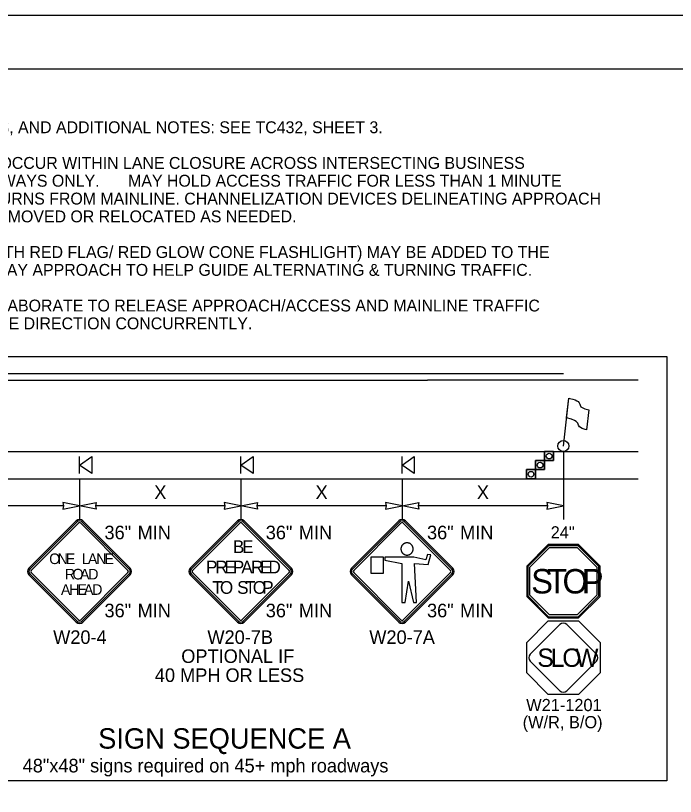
# Model space of a CAD drawing. Extents: x 99999.1 to 100095.7, y 99995 to 100010.7.
# Drawn here: x 100061.313 to 100065.2, y 100006.089 to 100010.687 of the extents above; entities that cross this region are included whole.
import ezdxf

# ---------------------------------------------------------------- set-up
doc = ezdxf.new("R2010")
doc.units = 0
for name, color, linetype in [('RD_ED_ShoulderPavedEdge', 7, 'Continuous'), ('RD_MK_LineDblYellowCenter', 7, 'Continuous'), ('RD_MK_LineEdgeWhite', 7, 'Continuous'), ('RD_MK_LineNoPass', 7, 'Continuous'), ('RD_MK_LineSkipCenter', 7, 'Continuous'), ('SH_DE_DetailHeading2Text', 7, 'Continuous'), ('SH_GI_GeneralNotesBodyText', 7, 'Continuous'), ('SH_GI_PlotLimits', 7, 'Continuous'), ('SH_GI_SheetBorder', 7, 'Continuous'), ('TR_SN_ConstructionSigns', 7, 'Continuous'), ('TR_WZ_FlaggingStation', 7, 'Continuous'), ('TR_WZ_PortableSignMountBlk-Org', 7, 'Continuous'), ('TR_WZ_TrafficCone', 7, 'Continuous'), ('TR_WZ_WorkZoneDetails', 7, 'Continuous'), ('TR_WZ_WorkZoneTextCurrent', 7, 'Continuous')]:
    doc.layers.add(name, color=color, linetype=linetype)

msp = doc.modelspace()

# ---------------------------------------------------------------- linework, layer by layer
at = {"layer": 'RD_ED_ShoulderPavedEdge'}
msp.add_line((100060.3, 100007.9602), (100064.9804, 100007.9602), dxfattribs=at)
at = {"layer": 'RD_MK_LineDblYellowCenter'}
for p, q in [((100060.3, 100008.5802), (100063.7402, 100008.5802)), ((100060.3, 100008.5402), (100063.7402, 100008.5402))]:
    msp.add_line(p, q, dxfattribs=at)
at = {"layer": 'RD_MK_LineEdgeWhite'}
msp.add_line((100060.3, 100008.1202), (100064.9804, 100008.1202), dxfattribs=at)
at = {"layer": 'RD_MK_LineNoPass'}
msp.add_line((100063.7402, 100008.5802), (100064.5402, 100008.5802), dxfattribs=at)
at = {"layer": 'RD_MK_LineSkipCenter'}
msp.add_lwpolyline([(100064.9804, 100008.5402), (100063.7402, 100008.5402)], dxfattribs=at)
at = {"layer": 'SH_GI_PlotLimits'}
msp.add_lwpolyline([(100059.0625, 99999.6875), (100076.0625, 99999.6875), (100076.0625, 100010.6875), (100059.0625, 100010.6875)], close=True, dxfattribs=at)
at = {"layer": 'SH_GI_SheetBorder'}
msp.add_line((100060, 100010.375), (100075.75, 100010.375), dxfattribs=at)
at = {"layer": 'TR_SN_ConstructionSigns'}
for p, q in [((100061.6703, 100007.712), (100061.3919, 100007.4336)), ((100061.6758, 100007.7065), (100061.3974, 100007.428)), ((100061.4051, 100007.4203), (100061.6835, 100007.6987)), ((100061.6968, 100007.6987), (100061.9752, 100007.4203)), ((100061.9829, 100007.428), (100061.7045, 100007.7065)), ((100061.9885, 100007.4336), (100061.71, 100007.712)), ((100062.6203, 100007.712), (100062.3419, 100007.4336)), ((100062.6258, 100007.7065), (100062.3474, 100007.428)), ((100062.3551, 100007.4203), (100062.6335, 100007.6987)), ((100062.6468, 100007.6987), (100062.9252, 100007.4203)), ((100062.9329, 100007.428), (100062.6545, 100007.7065)), ((100062.9385, 100007.4336), (100062.66, 100007.712)), ((100063.5703, 100007.712), (100063.2919, 100007.4336)), ((100063.5758, 100007.7065), (100063.2974, 100007.428)), ((100063.3051, 100007.4203), (100063.5835, 100007.6987)), ((100063.5968, 100007.6987), (100063.8752, 100007.4203)), ((100063.8829, 100007.428), (100063.6045, 100007.7065)), ((100063.8885, 100007.4336), (100063.61, 100007.712)), ((100063.6071, 100007.5803), (100063.6053, 100007.5796)), ((100063.6089, 100007.5809), (100063.6071, 100007.5803)), ((100063.6108, 100007.5814), (100063.6089, 100007.5809)), ((100063.6127, 100007.5818), (100063.6108, 100007.5814)), ((100063.6146, 100007.5821), (100063.6127, 100007.5818)), ((100063.6164, 100007.5823), (100063.6146, 100007.5821)), ((100063.6184, 100007.5824), (100063.6164, 100007.5823)), ((100063.6203, 100007.5824), (100063.6184, 100007.5824)), ((100063.6222, 100007.5823), (100063.6203, 100007.5824)), ((100063.6241, 100007.5821), (100063.6222, 100007.5823)), ((100063.626, 100007.5818), (100063.6241, 100007.5821)), ((100063.6279, 100007.5814), (100063.626, 100007.5818)), ((100063.6297, 100007.5809), (100063.6279, 100007.5814)), ((100063.6316, 100007.5803), (100063.6297, 100007.5809)), ((100063.6333, 100007.5796), (100063.6316, 100007.5803)), ((100063.5835, 100007.5502), (100063.5833, 100007.5483)), ((100063.5833, 100007.5483), (100063.5833, 100007.5464)), ((100063.5833, 100007.5464), (100063.5833, 100007.5445)), ((100063.5833, 100007.5445), (100063.5835, 100007.5426)), ((100063.5838, 100007.5522), (100063.5835, 100007.5502)), ((100063.5835, 100007.5426), (100063.5838, 100007.5407)), ((100063.5842, 100007.554), (100063.5838, 100007.5522)), ((100063.5838, 100007.5407), (100063.5842, 100007.5388)), ((100063.5846, 100007.5559), (100063.5842, 100007.554)), ((100063.5842, 100007.5388), (100063.5846, 100007.5369)), ((100063.5852, 100007.5577), (100063.5846, 100007.5559)), ((100063.5846, 100007.5369), (100063.5852, 100007.5351)), ((100063.5858, 100007.5595), (100063.5852, 100007.5577)), ((100063.5852, 100007.5351), (100063.5858, 100007.5333)), ((100063.5865, 100007.5613), (100063.5858, 100007.5595)), ((100063.5873, 100007.563), (100063.5865, 100007.5613)), ((100063.5883, 100007.5647), (100063.5873, 100007.563)), ((100063.5894, 100007.5664), (100063.5883, 100007.5647)), ((100063.5904, 100007.5679), (100063.5894, 100007.5664)), ((100063.5916, 100007.5694), (100063.5904, 100007.5679)), ((100063.5929, 100007.5709), (100063.5916, 100007.5694)), ((100063.5942, 100007.5722), (100063.5929, 100007.5709)), ((100063.5956, 100007.5735), (100063.5942, 100007.5722)), ((100063.5971, 100007.5747), (100063.5956, 100007.5735)), ((100063.5986, 100007.5759), (100063.5971, 100007.5747)), ((100063.6002, 100007.5769), (100063.5986, 100007.5759)), ((100063.6019, 100007.5779), (100063.6002, 100007.5769)), ((100063.6036, 100007.5788), (100063.6019, 100007.5779)), ((100063.6053, 100007.5796), (100063.6036, 100007.5788)), ((100063.6351, 100007.5788), (100063.6333, 100007.5796)), ((100063.6368, 100007.5779), (100063.6351, 100007.5788)), ((100063.6385, 100007.5769), (100063.6368, 100007.5779)), ((100063.64, 100007.5759), (100063.6385, 100007.5769)), ((100063.6416, 100007.5747), (100063.64, 100007.5759)), ((100063.643, 100007.5735), (100063.6416, 100007.5747)), ((100063.6445, 100007.5722), (100063.643, 100007.5735)), ((100063.6458, 100007.5709), (100063.6445, 100007.5722)), ((100063.647, 100007.5694), (100063.6458, 100007.5709)), ((100063.6482, 100007.5679), (100063.647, 100007.5694)), ((100063.6494, 100007.5664), (100063.6482, 100007.5679)), ((100063.6504, 100007.5647), (100063.6494, 100007.5664)), ((100063.6513, 100007.563), (100063.6504, 100007.5647)), ((100063.6521, 100007.5613), (100063.6513, 100007.563)), ((100063.6529, 100007.5595), (100063.6521, 100007.5613)), ((100063.6535, 100007.5577), (100063.6529, 100007.5595)), ((100063.6529, 100007.5333), (100063.6535, 100007.5351)), ((100063.6541, 100007.5559), (100063.6535, 100007.5577)), ((100063.6535, 100007.5351), (100063.6541, 100007.5369)), ((100063.6545, 100007.554), (100063.6541, 100007.5559)), ((100063.6541, 100007.5369), (100063.6545, 100007.5388)), ((100063.6549, 100007.5522), (100063.6545, 100007.554)), ((100063.6545, 100007.5388), (100063.6549, 100007.5407)), ((100063.6552, 100007.5502), (100063.6549, 100007.5522)), ((100063.6549, 100007.5407), (100063.6552, 100007.5426)), ((100063.6553, 100007.5483), (100063.6552, 100007.5502)), ((100063.6552, 100007.5426), (100063.6553, 100007.5445)), ((100063.6554, 100007.5464), (100063.6553, 100007.5483)), ((100063.6553, 100007.5445), (100063.6554, 100007.5464)), ((100064.4506, 100007.5722), (100064.3241, 100007.4457)), ((100064.4534, 100007.5655), (100064.3308, 100007.4429)), ((100064.3421, 100007.4383), (100064.4581, 100007.5542)), ((100064.6295, 100007.5722), (100064.4506, 100007.5722)), ((100064.6267, 100007.5655), (100064.4534, 100007.5655)), ((100064.4581, 100007.5542), (100064.6221, 100007.5542)), ((100064.6221, 100007.5542), (100064.7381, 100007.4383)), ((100064.7493, 100007.4429), (100064.6267, 100007.5655)), ((100064.7561, 100007.4457), (100064.6295, 100007.5722)), ((100063.4059, 100007.4991), (100063.4059, 100007.4044)), ((100063.4812, 100007.4991), (100063.4059, 100007.4991)), ((100063.4812, 100007.4044), (100063.4812, 100007.4991)), ((100063.6596, 100007.4991), (100063.4882, 100007.4991)), ((100063.4882, 100007.4991), (100063.4882, 100007.481)), ((100063.5858, 100007.5333), (100063.5865, 100007.5315)), ((100063.5865, 100007.5315), (100063.5873, 100007.5298)), ((100063.5873, 100007.5298), (100063.5883, 100007.5281)), ((100063.5883, 100007.5281), (100063.5894, 100007.5265)), ((100063.5894, 100007.5265), (100063.5904, 100007.5249)), ((100063.5904, 100007.5249), (100063.5916, 100007.5234)), ((100063.5916, 100007.5234), (100063.5929, 100007.522)), ((100063.5929, 100007.522), (100063.5942, 100007.5206)), ((100063.5942, 100007.5206), (100063.5956, 100007.5193)), ((100063.5956, 100007.5193), (100063.5971, 100007.5181)), ((100063.5971, 100007.5181), (100063.5986, 100007.5169)), ((100063.5986, 100007.5169), (100063.6002, 100007.5159)), ((100063.6002, 100007.5159), (100063.6019, 100007.5149)), ((100063.6019, 100007.5149), (100063.6036, 100007.514)), ((100063.6036, 100007.514), (100063.6053, 100007.5132)), ((100063.6053, 100007.5132), (100063.6071, 100007.5125)), ((100063.6071, 100007.5125), (100063.6089, 100007.5119)), ((100063.6089, 100007.5119), (100063.6108, 100007.5114)), ((100063.6108, 100007.5114), (100063.6127, 100007.511)), ((100063.6127, 100007.511), (100063.6146, 100007.5107)), ((100063.6146, 100007.5107), (100063.6164, 100007.5105)), ((100063.6164, 100007.5105), (100063.6184, 100007.5104)), ((100063.6184, 100007.5104), (100063.6203, 100007.5104)), ((100063.6203, 100007.5104), (100063.6222, 100007.5105)), ((100063.6222, 100007.5105), (100063.6241, 100007.5107)), ((100063.6241, 100007.5107), (100063.626, 100007.511)), ((100063.626, 100007.511), (100063.6279, 100007.5114)), ((100063.6279, 100007.5114), (100063.6297, 100007.5119)), ((100063.6297, 100007.5119), (100063.6316, 100007.5125)), ((100063.6316, 100007.5125), (100063.6333, 100007.5132)), ((100063.6333, 100007.5132), (100063.6351, 100007.514)), ((100063.6351, 100007.514), (100063.6368, 100007.5149)), ((100063.6368, 100007.5149), (100063.6385, 100007.5159)), ((100063.6385, 100007.5159), (100063.64, 100007.5169)), ((100063.64, 100007.5169), (100063.6416, 100007.5181)), ((100063.6416, 100007.5181), (100063.643, 100007.5193)), ((100063.643, 100007.5193), (100063.6445, 100007.5206)), ((100063.6445, 100007.5206), (100063.6458, 100007.522)), ((100063.6458, 100007.522), (100063.647, 100007.5234)), ((100063.647, 100007.5234), (100063.6482, 100007.5249)), ((100063.6482, 100007.5249), (100063.6494, 100007.5265)), ((100063.6494, 100007.5265), (100063.6504, 100007.5281)), ((100063.6504, 100007.5281), (100063.6513, 100007.5298)), ((100063.6513, 100007.5298), (100063.6521, 100007.5315)), ((100063.6521, 100007.5315), (100063.6529, 100007.5333)), ((100063.7291, 100007.482), (100063.6596, 100007.4991)), ((100063.7388, 100007.5148), (100063.7291, 100007.482)), ((100063.7588, 100007.5112), (100063.7388, 100007.5148)), ((100063.7438, 100007.4544), (100063.7588, 100007.5112)), ((100063.4882, 100007.481), (100063.5877, 100007.4612)), ((100063.5877, 100007.4612), (100063.5877, 100007.2309)), ((100063.6759, 100007.2309), (100063.6628, 100007.4613)), ((100063.6628, 100007.4613), (100063.7438, 100007.4544)), ((100064.3241, 100007.4457), (100064.3241, 100007.2668)), ((100064.3308, 100007.4429), (100064.3308, 100007.2696)), ((100064.7493, 100007.2696), (100064.7493, 100007.4429)), ((100064.7561, 100007.2668), (100064.7561, 100007.4457)), ((100061.3974, 100007.3993), (100061.6758, 100007.1209)), ((100061.6835, 100007.1286), (100061.4051, 100007.4071)), ((100061.9752, 100007.4071), (100061.6968, 100007.1286)), ((100061.7045, 100007.1209), (100061.9829, 100007.3993)), ((100062.3474, 100007.3993), (100062.6258, 100007.1209)), ((100062.6335, 100007.1286), (100062.3551, 100007.4071)), ((100062.9252, 100007.4071), (100062.6468, 100007.1286)), ((100062.6545, 100007.1209), (100062.9329, 100007.3993)), ((100063.2974, 100007.3993), (100063.5758, 100007.1209)), ((100063.5835, 100007.1286), (100063.3051, 100007.4071)), ((100063.4059, 100007.4044), (100063.4812, 100007.4044)), ((100063.8752, 100007.4071), (100063.5968, 100007.1286)), ((100063.6045, 100007.1209), (100063.8829, 100007.3993)), ((100064.3421, 100007.2742), (100064.3421, 100007.4383)), ((100064.7381, 100007.4383), (100064.7381, 100007.2742)), ((100061.3919, 100007.3938), (100061.6703, 100007.1154)), ((100061.71, 100007.1154), (100061.9885, 100007.3938)), ((100062.3419, 100007.3938), (100062.6203, 100007.1154)), ((100062.66, 100007.1154), (100062.9385, 100007.3938)), ((100063.2919, 100007.3938), (100063.5703, 100007.1154)), ((100063.6079, 100007.2309), (100063.6276, 100007.3576)), ((100063.61, 100007.1154), (100063.8885, 100007.3938)), ((100063.6276, 100007.3576), (100063.6579, 100007.2309)), ((100064.3241, 100007.2668), (100064.4506, 100007.1402)), ((100064.3308, 100007.2696), (100064.4534, 100007.147)), ((100064.4581, 100007.1582), (100064.3421, 100007.2742)), ((100064.7381, 100007.2742), (100064.6221, 100007.1582)), ((100064.6267, 100007.147), (100064.7493, 100007.2696)), ((100064.6295, 100007.1402), (100064.7561, 100007.2668)), ((100063.5877, 100007.2309), (100063.6079, 100007.2309)), ((100063.6579, 100007.2309), (100063.6759, 100007.2309)), ((100064.4506, 100007.1402), (100064.6295, 100007.1402)), ((100064.4534, 100007.147), (100064.6267, 100007.147)), ((100064.6221, 100007.1582), (100064.4581, 100007.1582)), ((100064.5197, 100007.1019), (100064.3444, 100006.9266)), ((100064.7357, 100006.9266), (100064.5604, 100007.1019)), ((100064.3444, 100006.8859), (100064.5197, 100006.7106)), ((100064.5604, 100006.7106), (100064.7357, 100006.8859))]:
    msp.add_line(p, q, dxfattribs=at)
msp.add_lwpolyline([(100064.7561, 100006.9957), (100064.7561, 100006.8168), (100064.6295, 100006.6902), (100064.4506, 100006.6902), (100064.3241, 100006.8168), (100064.3241, 100006.9957), (100064.4506, 100007.1222), (100064.6295, 100007.1222)], close=True, dxfattribs=at)
for centre, radius, start, end in [((100061.6902, 100007.6921), 0.0281, 45, 135), ((100062.6402, 100007.6921), 0.0281, 45, 135), ((100063.5902, 100007.6921), 0.0281, 45, 135), ((100061.6902, 100007.6921), 0.0203, 45, 135), ((100061.6902, 100007.6921), 0.00937, 45, 135), ((100062.6402, 100007.6921), 0.0203, 45, 135), ((100062.6402, 100007.6921), 0.00937, 45, 135), ((100063.5902, 100007.6921), 0.0203, 45, 135), ((100063.5902, 100007.6921), 0.00937, 45, 135), ((100061.4117, 100007.4137), 0.0281, 135, 225), ((100061.4117, 100007.4137), 0.0203, 135, 225), ((100061.4117, 100007.4137), 0.00937, 135, 225), ((100061.9686, 100007.4137), 0.00937, 315, 45), ((100061.9686, 100007.4137), 0.0203, 315, 45), ((100061.9686, 100007.4137), 0.0281, 315, 45), ((100062.3617, 100007.4137), 0.0281, 135, 225), ((100062.3617, 100007.4137), 0.0203, 135, 225), ((100062.3617, 100007.4137), 0.00937, 135, 225), ((100062.9186, 100007.4137), 0.00937, 315, 45), ((100062.9186, 100007.4137), 0.0203, 315, 45), ((100062.9186, 100007.4137), 0.0281, 315, 45), ((100063.3117, 100007.4137), 0.0281, 135, 225), ((100063.3117, 100007.4137), 0.0203, 135, 225), ((100063.3117, 100007.4137), 0.00937, 135, 225), ((100063.8686, 100007.4137), 0.00937, 315, 45), ((100063.8686, 100007.4137), 0.0203, 315, 45), ((100063.8686, 100007.4137), 0.0281, 315, 45), ((100061.6902, 100007.1353), 0.0203, 225, 315), ((100061.6902, 100007.1353), 0.00937, 225, 315), ((100062.6402, 100007.1353), 0.0203, 225, 315), ((100062.6402, 100007.1353), 0.00937, 225, 315), ((100063.5902, 100007.1353), 0.0203, 225, 315), ((100063.5902, 100007.1353), 0.00937, 225, 315), ((100061.6902, 100007.1353), 0.0281, 225, 315), ((100062.6402, 100007.1353), 0.0281, 225, 315), ((100063.5902, 100007.1353), 0.0281, 225, 315), ((100064.5401, 100007.0815), 0.0288, 45, 135), ((100064.3648, 100006.9062), 0.0288, 135, 225), ((100064.7153, 100006.9062), 0.0288, 315, 45), ((100064.5401, 100006.731), 0.0288, 225, 315)]:
    msp.add_arc(centre, radius, start, end, dxfattribs=at)
at = {"layer": 'TR_WZ_FlaggingStation'}
for p, q in [((100064.5402, 100008.1527), (100064.5722, 100008.4337)), ((100064.5592, 100008.3196), (100064.5723, 100008.434)), ((100064.6902, 100008.3662), (100064.6769, 100008.249)), ((100064.5592, 100008.3196), (100064.5592, 100008.3196))]:
    msp.add_line(p, q, dxfattribs=at)
for points in [[(100064.5723, 100008.434), (100064.578, 100008.4327), (100064.5958, 100008.4293), (100064.6097, 100008.4251), (100064.6193, 100008.419), (100064.6279, 100008.4143), (100064.6335, 100008.4075), (100064.6378, 100008.3996), (100064.6383, 100008.3934), (100064.6437, 100008.3842), (100064.6545, 100008.3768), (100064.6669, 100008.3716), (100064.6902, 100008.3662)], [(100064.6769, 100008.249), (100064.6687, 100008.2504), (100064.6511, 100008.255), (100064.6354, 100008.2655), (100064.6289, 100008.2761), (100064.625, 100008.2864), (100064.6159, 100008.2973), (100064.6049, 100008.3035), (100064.5876, 100008.3106), (100064.5592, 100008.3196)]]:
    msp.add_lwpolyline(points, dxfattribs=at)
msp.add_circle((100064.5402, 100008.1527), 0.0325, dxfattribs=at)
at = {"layer": 'TR_WZ_PortableSignMountBlk-Org'}
for p, q in [((100061.6902, 100007.9902), (100061.6902, 100008.0902)), ((100062.6402, 100007.9902), (100062.6402, 100008.0902)), ((100063.5902, 100007.9902), (100063.5902, 100008.0902))]:
    msp.add_line(p, q, dxfattribs=at)
for points in [[(100061.6902, 100008.0401), (100061.762, 100008.0902), (100061.762, 100007.9902)], [(100062.6402, 100008.0401), (100062.712, 100008.0902), (100062.712, 100007.9902)], [(100063.5902, 100008.0401), (100063.662, 100008.0902), (100063.662, 100007.9902)]]:
    msp.add_lwpolyline(points, close=True, dxfattribs=at)
at = {"layer": 'TR_WZ_TrafficCone'}
for points in [[(100064.4295, 100008.1202), (100064.4828, 100008.1202), (100064.4828, 100008.0669), (100064.4295, 100008.0669), (100064.4295, 100008.1202)], [(100064.4295, 100008.0669), (100064.4828, 100008.0669), (100064.4828, 100008.1202), (100064.4295, 100008.1202), (100064.4295, 100008.0669)], [(100064.3762, 100008.0669), (100064.4295, 100008.0669), (100064.4295, 100008.0136), (100064.3762, 100008.0136), (100064.3762, 100008.0669)], [(100064.3762, 100008.0136), (100064.4295, 100008.0136), (100064.4295, 100008.0669), (100064.3762, 100008.0669), (100064.3762, 100008.0136)], [(100064.3228, 100008.0136), (100064.3762, 100008.0136), (100064.3762, 100007.9602), (100064.3228, 100007.9602), (100064.3228, 100008.0136)], [(100064.3228, 100007.9602), (100064.3762, 100007.9602), (100064.3762, 100008.0136), (100064.3228, 100008.0136), (100064.3228, 100007.9602)]]:
    msp.add_lwpolyline(points, dxfattribs=at)
for centre in [(100064.4562, 100008.0936), (100064.4028, 100008.0402), (100064.3495, 100007.9869)]:
    msp.add_circle(centre, 0.0167, dxfattribs=at)
at = {"layer": 'TR_WZ_WorkZoneDetails'}
for p, q in [((100064.5402, 100008.1202), (100064.5402, 100007.7202)), ((100061.6902, 100007.9602), (100061.6902, 100007.7202)), ((100062.6402, 100007.9602), (100062.6402, 100007.7202)), ((100063.5902, 100007.9602), (100063.5902, 100007.7202)), ((100061.5964, 100007.8002), (100060.8339, 100007.8002)), ((100062.5464, 100007.8002), (100061.7839, 100007.8002)), ((100063.4964, 100007.8002), (100062.7339, 100007.8002)), ((100064.4464, 100007.8002), (100063.6839, 100007.8002))]:
    msp.add_line(p, q, dxfattribs=at)
for points in [[(100061.6902, 100007.8002), (100061.5919, 100007.8195), (100061.5964, 100007.8002), (100061.5919, 100007.781)], [(100061.6902, 100007.8002), (100061.7884, 100007.8195), (100061.7839, 100007.8002), (100061.7884, 100007.781)], [(100062.6402, 100007.8002), (100062.5419, 100007.8195), (100062.5464, 100007.8002), (100062.5419, 100007.781)], [(100062.6402, 100007.8002), (100062.7384, 100007.8195), (100062.7339, 100007.8002), (100062.7384, 100007.781)], [(100063.5902, 100007.8002), (100063.4919, 100007.8195), (100063.4964, 100007.8002), (100063.4919, 100007.781)], [(100063.5902, 100007.8002), (100063.6884, 100007.8195), (100063.6839, 100007.8002), (100063.6884, 100007.781)], [(100064.5402, 100007.8002), (100064.4419, 100007.8195), (100064.4464, 100007.8002), (100064.4419, 100007.781)]]:
    msp.add_lwpolyline(points, close=True, dxfattribs=at)
at = {"layer": 'TR_WZ_WorkZoneTextCurrent'}
msp.add_lwpolyline([(100060.1, 100008.6802), (100065.15, 100008.6802), (100065.15, 100006.1804), (100060.1, 100006.1804)], close=True, dxfattribs=at)

# ---------------------------------------------------------------- texts
at = {"layer": 'SH_DE_DetailHeading2Text'}
msp.add_text('SIGN SEQUENCE A', height=0.12, rotation=360, dxfattribs=at).set_placement((100061.7998, 100006.3705))
at = {"layer": 'SH_GI_GeneralNotesBodyText'}
for s, p in [('13. FOR LEGEND, TABLES, AND ADDITIONAL NOTES: SEE TC432, SHEET 3.', (100060.1, 100009.995)), ('14. WORK MAY BRIEFLY OCCUR WITHIN LANE CLOSURE ACROSS INTERSECTING BUSINESS ', (100060.1, 100009.785)), ('ACCESSES AND DRIVEWAYS ONLY. ', (100060.18, 100009.68)), ('MAY HOLD ACCESS TRAFFIC FOR LESS THAN 1 MINUTE', (100061.9762, 100009.68)), ('WHILE RESTRICTING TURNS FROM MAINLINE. CHANNELIZATION DEVICES DELINEATING APPROACH ', (100060.18, 100009.575)), ('OR ACCESS MAY BE REMOVED OR RELOCATED AS NEEDED.', (100060.18, 100009.47)), ('15. SINGLE FLAGGER (WITH RED FLAG/ RED GLOW CONE FLASHLIGHT) MAY BE ADDED TO THE ', (100060.1, 100009.26)), ('INTERSECTING ROADWAY APPROACH TO HELP GUIDE ALTERNATING & TURNING TRAFFIC.', (100060.18, 100009.155)), ('16. FLAGGERS MAY COLLABORATE TO RELEASE APPROACH/ACCESS AND MAINLINE TRAFFIC ', (100060.1, 100008.945)), ('TRAVELING IN THE SAME DIRECTION CONCURRENTLY.', (100060.18, 100008.84))]:
    msp.add_text(s, height=0.07, rotation=360, dxfattribs=at).set_placement(p)
at = {"layer": 'TR_SN_ConstructionSigns'}
for s, height, p in [('36"', 0.08, (100061.8369, 100007.6035)), ('MIN', 0.08, (100062.0319, 100007.6035)), ('36"', 0.08, (100062.7869, 100007.6035)), ('MIN', 0.08, (100062.9819, 100007.6035)), ('36"', 0.08, (100063.7369, 100007.6035)), ('MIN', 0.08, (100063.9319, 100007.6035)), ('36"', 0.08, (100061.8369, 100007.1439)), ('MIN', 0.08, (100062.0319, 100007.1439)), ('36"', 0.08, (100062.7869, 100007.1439)), ('MIN', 0.08, (100062.9819, 100007.1439)), ('36"', 0.08, (100063.7369, 100007.1439)), ('MIN', 0.08, (100063.9319, 100007.1439)), ('W20-4', 0.08, (100061.5347, 100006.9871)), ('W20-7B', 0.08, (100062.4432, 100006.9871)), ('W20-7A', 0.08, (100063.3969, 100006.9871)), ('OPTIONAL IF', 0.08, (100062.2892, 100006.8751)), ('40 MPH OR LESS', 0.08, (100062.1337, 100006.7631)), ('W21-1201', 0.072, (100064.3213, 100006.5913)), ('(W/R, B/O)', 0.072, (100064.3004, 100006.4905))]:
    msp.add_text(s, height=height, rotation=360, dxfattribs=at).set_placement(p)
for s, height, p in [('24"', 0.072, (100064.4654, 100007.6082)), ('B', 0.075, (100062.5939, 100007.5222)), ('E', 0.075, (100062.6482, 100007.5222)), ('O', 0.0625, (100061.5114, 100007.4574)), ('N', 0.0625, (100061.5608, 100007.4574)), ('E', 0.0625, (100061.6095, 100007.4574)), ('L', 0.0625, (100061.7039, 100007.4574)), ('A', 0.0625, (100061.7395, 100007.4574)), ('N', 0.0625, (100061.7883, 100007.4574)), ('E', 0.0625, (100061.837, 100007.4574)), ('P', 0.075, (100062.4353, 100007.4022)), ('R', 0.075, (100062.4905, 100007.4022)), ('E', 0.075, (100062.5437, 100007.4022)), ('P', 0.075, (100062.5932, 100007.4022)), ('A', 0.075, (100062.6431, 100007.4022)), ('R', 0.075, (100062.7004, 100007.4022)), ('E', 0.075, (100062.7536, 100007.4022)), ('D', 0.075, (100062.8031, 100007.4022)), ('R', 0.0625, (100061.6039, 100007.3668)), ('O', 0.0625, (100061.6483, 100007.3668)), ('A', 0.0625, (100061.6927, 100007.3668)), ('D', 0.0625, (100061.7414, 100007.3668)), ('S', 0.144, (100064.3507, 100007.2842)), ('T', 0.144, (100064.4443, 100007.2842)), ('O', 0.144, (100064.535, 100007.2842)), ('P', 0.144, (100064.6488, 100007.2842)), ('T', 0.075, (100062.4719, 100007.2822)), ('O', 0.075, (100062.517, 100007.2822)), ('S', 0.075, (100062.6185, 100007.2822)), ('T', 0.075, (100062.6656, 100007.2822)), ('O', 0.075, (100062.7107, 100007.2822)), ('P', 0.075, (100062.7664, 100007.2822)), ('A', 0.0625, (100061.5808, 100007.2762)), ('H', 0.0625, (100061.6295, 100007.2762)), ('E', 0.0625, (100061.6783, 100007.2762)), ('A', 0.0625, (100061.7158, 100007.2762)), ('D', 0.0625, (100061.7645, 100007.2762)), ('S', 0.108, (100064.3873, 100006.8522)), ('L', 0.108, (100064.4661, 100006.8522)), ('O', 0.108, (100064.5341, 100006.8522)), ('W', 0.108, (100064.6108, 100006.8522))]:
    msp.add_text(s, height=height, dxfattribs=at).set_placement(p)
at = {"layer": 'TR_WZ_WorkZoneTextCurrent'}
for p in [(100062.1304, 100007.8402), (100063.0804, 100007.8402), (100064.0304, 100007.8402)]:
    msp.add_text('X', height=0.08, rotation=360, dxfattribs=at).set_placement(p)
msp.add_text('48"x48" signs required on 45+ mph roadways', height=0.08, dxfattribs=at).set_placement((100061.3551, 100006.2305))

doc.saveas('drawing.dxf')
